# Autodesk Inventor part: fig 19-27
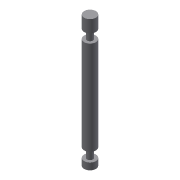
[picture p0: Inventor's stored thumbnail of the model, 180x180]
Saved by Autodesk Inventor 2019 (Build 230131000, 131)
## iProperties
Created: 2013-07
Part Number: fig 19-27
Material: Generic
Document SubType Name: Modeling
Designer: CADCIM
Density: 1 g/cm^3
Appearance: Default
Author: CADCIM
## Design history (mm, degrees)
sketch "Sketch3"
  geometry: L1 (0, 19.325)-(1.664, 19.325); L2 (1.664, 19.325)-(1.664, 15.806); L3 (1.664, 15.806)-(0.832, 15.806); L4 (0.832, 15.806)-(0.832, 13.31); L5 (0.832, 13.31)-(1.664, 13.31); L6 (1.664, 13.31)-(1.664, -13.31); L7 (1.664, -13.31)-(0.832, -13.31); L8 (0.832, -13.31)-(0.832, -15.934); L9 (0.832, -15.934)-(1.664, -15.934); L10 (1.664, -15.934)-(1.664, -17.853); L11 (1.664, -17.853)-(0, -17.853); L12 (0, -17.853)-(0, 19.325); 1 further point
  constraints: 24 end point, 8 perpendicular, 6 point on line, 1 horizontal
revolve "Revolution1" sketch "Sketch3" stored, may be unused: angle "d8" = 90 deg
body "Solid2"
